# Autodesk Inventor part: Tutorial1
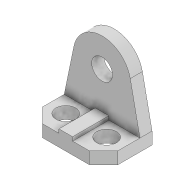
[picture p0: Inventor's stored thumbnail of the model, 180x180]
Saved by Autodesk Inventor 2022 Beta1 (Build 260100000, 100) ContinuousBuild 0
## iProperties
Created: 2021-03
Part Number: Tutorial1
Material: Generic
Document SubType Name: Modeling
Designer: ASUS Laptop
Density: 1 g/cm^3
Appearance: Default
Author: ASUS Laptop
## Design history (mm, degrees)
sketch "Sketch1"
  geometry: L1 (0, 0)-(-200, 0); L2 (-200, 0)-(-200, 90); L3 (-200, 90)-(-162, 128); L4 (-162, 128)-(-38, 128); L5 (-38, 128)-(0, 90); L6 (0, 90)-(0, 0); L7 (-154, 74)-(-31.817, 74); C1 r 26 at (-154, 74); C2 r 26 at (-46, 74); 1 further point
  constraints: 14 end point, 2 centre point, 2 horizontal, 2 parallel, 2 perpendicular, 1 coincident, 1 equal radius, 1 point on line
  dimensions: "d0" = 128 distance between parallel lines of L4 L1; "d1" = 90 distance of L1.end L2.end; "d2" = 124 distance of L3.end L4.end; "d3" = 38 horizontal distance of L3.end L2.end; "d4" = 38 horizontal distance of L5.end L4.end; "d5" = 46 distance from line of L7.start L2; "d6" = 46 distance from line of L6 C2.centre; "d7" = 74 distance from line of L7.start L1; "d8" = 52 diameter of C2
extrude "Extrusion1" new body sketch "Sketch1" distance "d9" = 32; taper "d10" = 0 deg
sketch "Sketch2"
  geometry: L1 (200, 32)-(162, 32) reference; L2 (200, 32)-(174.418, 155.424); L3 (38, 32)-(0, 32) reference; L4 (25.582, 155.424)-(0, 32); L5 (0, 32)-(200, 32); L6 (162, 0)-(38, 0) reference; L7 (100, 0)-(100, 176.194); C1 r 27.5 at (100, 140); A1 r 76 centre (100, 140) between (174.418, 155.424) and (25.582, 155.424); 3 further points
  constraints: 8 end point, 2 centre point, 2 point on circle, 2 tangent, 1 coincident, 1 collinear, 1 midpoint, 1 vertical, 1 other
  dimensions: "d11" = 76 radius of A1; "d12" = 108 distance from line of A1.centre L5; "d13" = 55 diameter of C1
extrude "Extrusion2" join sketch "Sketch2" distance "d14" = 32; taper "d15" = 0 deg
sketch "Sketch3"
  geometry: 1 further point
sketch "Sketch4"
  geometry: L1 (0, 32)-(124, 32) reference; L2 (44, 32)-(80, 32); L3 (80, 32)-(80, 42); L4 (80, 42)-(44, 42); L5 (44, 42)-(44, 32); L6 (-38, 0)-(-38, 32) reference; 1 further point
  constraints: 8 end point, 2 parallel, 1 horizontal, 1 perpendicular, 1 point on line
  dimensions: "d16" = 36 distance of L3.end L4.end; "d17" = 10 distance of L4.end L2.start; "d18" = 82 distance between parallel lines of L5 L6
extrude "Extrusion3" join sketch "Sketch4" stored distance "d19" = 32; taper "d20" = 0 deg
body "Solid1"
